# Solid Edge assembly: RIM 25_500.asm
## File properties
Title: Zylinder
Author: ahadarics
Template: iso metric assembly.asm
Last saved by: ahadarics
Revision: 23
Application: Solid Edge
Username: ahadarics
Dokumentum tartalom típus: 1
Document Number: RIM 25/500
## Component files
Profilrohr.par
Kolbenstange.par
Kit_1.par
Kit_2.par
Mutter_1.par
Mutter_2.par
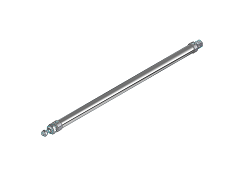
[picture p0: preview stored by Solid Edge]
